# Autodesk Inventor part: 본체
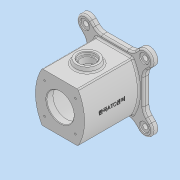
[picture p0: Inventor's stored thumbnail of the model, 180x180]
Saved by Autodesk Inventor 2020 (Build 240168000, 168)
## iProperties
Created: 2022-01
Part Number: 본체
Material: 일반
Document SubType Name: Modeling
Designer: user
Density: 1 g/cm^3
Appearance: 기본값
Mass: 459.178 g
Surface Area: 908.253 cm^2
Volume: 459.178 cm^3
Author: user
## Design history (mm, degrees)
sketch "스케치1"
  geometry: L1 (-32.942, -45)-(32.942, -45); L2 (32.942, 45)-(-32.942, 45); L3 (-45, -45)-(45, 45); L4 (45, -45)-(-45, 45); A1 r 90 centre (45, 0) between (-32.942, 45) and (-32.942, -45); A2 r 90 centre (-45, 0) between (32.942, -45) and (32.942, 45); 5 further points
  constraints: 8 end point, 6 point on circle, 3 midpoint, 2 centre point, 2 coincident, 2 vertical alignment, 1 horizontal, 1 parallel, 1 perpendicular
  dimensions: "d0" = 90 distance of L4.end L3.end; "d1" = 90 distance of L3.end L4.start; "d10" = 90 radius of A2; "d11" = 90 radius of A1; "d12" = 45 deg angle of L2 L3; "d13" = 90 distance between parallel lines of L2 L1; "d14" = 45 distance from line of point (0, 0) L2; "d15" = 0 distance from line of L3.end L2; "d16" = 31.81981 distance from line of point (45, 0) L3; "d17" = 31.81981 distance from line of A1.centre L3; "d18" = 31.81981 distance from line of point (0, -45) L3; "d19" = 90 distance from line of L3.start L2
extrude "돌출1" new body sketch "스케치1" distance "d3" = 100; taper "d4" = 0 deg
sketch "스케치2"
  geometry: L1 (-53, -53)-(53, -53); L2 (53, -53)-(53, 53); L3 (53, 53)-(-53, 53); L4 (-53, 53)-(-53, -53); L5 (-53, -53)-(53, 53); L6 (53, -53)-(-53, 53); L7 (54.447, -54.447)-(-54.447, 54.447); L8 (65.054, -43.841)-(-43.841, 65.054); L9 (-65.054, 43.841)-(43.841, -65.054); L10 (-54.447, -54.447)-(54.447, 54.447); L11 (-43.841, -65.054)-(65.054, 43.841); L12 (43.841, 65.054)-(-65.054, -43.841); A1 r 77 centre (0, 0) between (-54.447, 54.447) and (54.447, 54.447); A2 r 15 centre (54.447, -54.447) between (43.841, -65.054) and (65.054, -43.841); A3 r 15 centre (-54.447, 54.447) between (-43.841, 65.054) and (-65.054, 43.841); A4 r 15 centre (-54.447, -54.447) between (-65.054, -43.841) and (-43.841, -65.054); A5 r 15 centre (54.447, 54.447) between (65.054, 43.841) and (43.841, 65.054); 9 further points
  constraints: 28 end point, 10 point on circle, 8 tangent, 5 centre point, 4 midpoint, 4 parallel, 2 point on line, 1 coincident, 1 horizontal, 1 perpendicular
  dimensions: "d5" = 106 distance of L3.end L2.end; "d6" = 106 distance of L2.end L1.end; "d7" = 154 diameter of A1; "d8" = 30 diameter of A3; "d9" = 30 diameter of A5
extrude "돌출2" join sketch "스케치2" distance "d20" = 10; taper "d21" = 0 deg
node "작업 평면1"
sketch "스케치3"
  geometry: L1 (31.787, -10)-(-31.787, -10) reference; L2 (31.787, 0)-(-31.787, 0) reference; C1 r 20 at (0, 50); 2 further points
  constraints: 1 centre point, 1 midpoint, 1 vertical alignment
  dimensions: "d23" = 40 diameter of C1; "d24" = 50 distance of point (0, 0) C1.centre
extrude "돌출3" join sketch "스케치3" stored distance "d25" = 10; taper "d26" = 15 deg
sketch "스케치4"
  geometry: C1 r 20 at (0, 0) reference; C2 r 15 at (0, 0); 1 further point
  constraints: 1 centre point, 1 coincident
  dimensions: "d27" = 30 diameter of C2
extrude "돌출4" cut sketch "스케치4" distance "d28" = 5; taper "d29" = 0 deg
sketch "스케치5"
  geometry: C1 r 15 at (0, 0) reference; C2 r 15 at (0, 0) reference; C3 r 12 at (0, 0); 1 further point
  constraints: 1 centre point, 1 coincident
  dimensions: "d30" = 24 diameter of C3
extrude "돌출5" cut sketch "스케치5" distance "d31" = 47.5; taper "d32" = 0 deg
sketch "스케치6"
  geometry: C1 r 25 at (0, 0); 1 further point
  constraints: 1 centre point, 1 coincident
  dimensions: "d33" = 50 diameter of C1
extrude "돌출6" cut sketch "스케치6" distance "d34" = 12; taper "d35" = 0 deg
sketch "스케치7"
  geometry: C1 r 37 at (0, 0); 1 further point
  constraints: 1 centre point, 1 coincident
  dimensions: "d36" = 74 diameter of C1
extrude "돌출7" cut sketch "스케치7" distance "d37" = 86; taper "d38" = 0 deg
sketch "스케치8"
  geometry: C1 r 25 at (0, 0); 1 further point
  constraints: 1 centre point, 1 coincident
  dimensions: "d39" = 50 diameter of C1
extrude "돌출8" cut sketch "스케치8" distance "d40" = 12; taper "d41" = 0 deg
sketch "스케치9"
  geometry: L1 (53, -31.787)-(65.054, -43.841) reference; L2 (53, 31.787)-(53, -31.787) reference; L3 (65.054, 43.841)-(53, 31.787) reference; L4 (31.787, 53)-(43.841, 65.054) reference; L5 (-31.787, 53)-(31.787, 53) reference; L6 (-43.841, 65.054)-(-31.787, 53) reference; L7 (-53, 31.787)-(-65.054, 43.841) reference; L8 (-53, -31.787)-(-53, 31.787) reference; L9 (-65.054, -43.841)-(-53, -31.787) reference; L10 (-31.787, -53)-(-43.841, -65.054) reference; L11 (31.787, -53)-(-31.787, -53) reference; L12 (43.841, -65.054)-(31.787, -53) reference; L13 (32.942, 45)-(-32.942, 45) reference; L14 (-32.942, -45)-(32.942, -45) reference; A1 r 15 centre (54.447, 54.447) between (65.054, 43.841) and (43.841, 65.054) reference; A2 r 15 centre (-54.447, 54.447) between (-43.841, 65.054) and (-65.054, 43.841) reference; A3 r 15 centre (-54.447, -54.447) between (-65.054, -43.841) and (-43.841, -65.054) reference; A4 r 15 centre (54.447, -54.447) between (43.841, -65.054) and (65.054, -43.841) reference; A5 r 90 centre (-45, 0) between (32.942, -45) and (32.942, 45) reference; A6 r 90 centre (45, 0) between (-32.942, 45) and (-32.942, -45) reference; 1 further point
  node "투영된 루프3"
hole "구멍1" sketch "스케치9" diameter "d42" = 9; stored, may be unused: countersink angle "d46" = 90 deg, drill point angle "d48" = 118 deg; dims "d43" = 33, "d44" = 18, "d45" = 2, "d47" = 34.05
hole "구멍2" sketch "스케치9" diameter "d49" = 9; stored, may be unused: countersink angle "d53" = 90 deg, drill point angle "d55" = 118 deg; dims "d50" = 33, "d51" = 18, "d52" = 2, "d54" = 34.05
hole "구멍3" sketch "스케치9" diameter "d56" = 9; stored, may be unused: countersink angle "d60" = 90 deg, drill point angle "d62" = 118 deg; dims "d57" = 33, "d58" = 18, "d59" = 2, "d61" = 34.05
hole "구멍4" sketch "스케치9" diameter "d63" = 9; stored, may be unused: countersink angle "d67" = 90 deg, drill point angle "d69" = 118 deg; dims "d64" = 33, "d65" = 18, "d66" = 2, "d68" = 34.05
sketch "스케치10" dims "d70" = 80
  geometry: L1 (-32.942, -45)-(32.942, -45) reference; L2 (32.942, 45)-(-32.942, 45) reference; L3 (0, 0)-(-79.741, 79.741); L4 (0, 0)-(78.475, 78.475); L5 (0, 0)-(0, 76.338); C1 r 25 at (0, 0) reference; A1 r 90 centre (-45, 0) between (32.942, -45) and (32.942, 45) reference; A2 r 90 centre (45, 0) between (-32.942, 45) and (-32.942, -45) reference; 2 further points
  constraints: 6 end point, 1 coincident, 1 point on line, 1 vertical, 3 other
  dimensions: "d71" = 45 deg angle of L5 L3; "d72" = 45 deg angle of L4 L5
hole "구멍5" sketch "스케치10" at (-28.284, 28.284) diameter "d73" = 3.242; stored, may be unused: countersink angle "d77" = 90 deg, drill point angle "d79" = 118 deg; dims "d74" = 8, "d75" = 18, "d76" = 2, "d78" = 10
sketch "스케치11"
  geometry: C1 r 1.621 at (-28.284, 28.284) reference; 1 further point
hole "구멍6" sketch "스케치11" at (-28.284, 28.284) diameter "d83" = 3.242; stored, may be unused: countersink angle "d87" = 90 deg, drill point angle "d89" = 118 deg; dims "d84" = 8, "d85" = 18, "d86" = 2, "d88" = 10
fillet "모깎기1" dims "d93" = 20
chamfer "모따기1" distance "d94" = 1; stored, may be unused: second distance "d95" = 2, angle "d96" = 45 deg
chamfer "모따기2" distance "d97" = 1; stored, may be unused: second distance "d98" = 2, angle "d99" = 45 deg
fillet "모깎기2" dims "d100" = 3
fillet "모깎기3" dims "d101" = 3
fillet "모깎기4" dims "d102" = 3
fillet "모깎기5" dims "d103" = 3
sketch "스케치12"
  geometry: L1 (53, 30)-(53, 70) reference; L2 (-26, -10)-(26, -10) reference; 2 further points
  constraints: 1 other
  dimensions: "d104" = 60 distance from line of L2 point (0, 50); "d105" = 53 distance from line of point (0, 50) L1
feature "엠보싱1" sketch "스케치12" dims "d0" = 90, "d1" = 90, "d5" = 106, "d6" = 106, "d7" = 154, "d8" = 30, "d9" = 30, "d10" = 90, "d11" = 90, "d12" = 45 deg, "d13" = 90, "d14" = 45, "d15" = 0, "d16" = 31.81981, "d17" = 31.81981, "d18" = 31.81981, "d19" = 90, "d106" = 0.5, "d107" = 0
fillet "모깎기6" dims "d108" = 3
node "솔리드1"
pattern_circular "원형 패턴1" dims angle "d81" = 360 deg
pattern_circular "원형 패턴2" dims angle "d91" = 360 deg
node "투영된 루프1"
node "투영된 루프2"
node "투영된 루프4"
feature "A9D066F2-1C7D-4E18-AEED-F7BC21143FA4" dims "d42" = 9, "d43" = 33, "d44" = 18, "d45" = 2, "d46" = 90 deg, "d47" = 34.05, "d48" = 118 deg
other parameters: "d22" = 53
